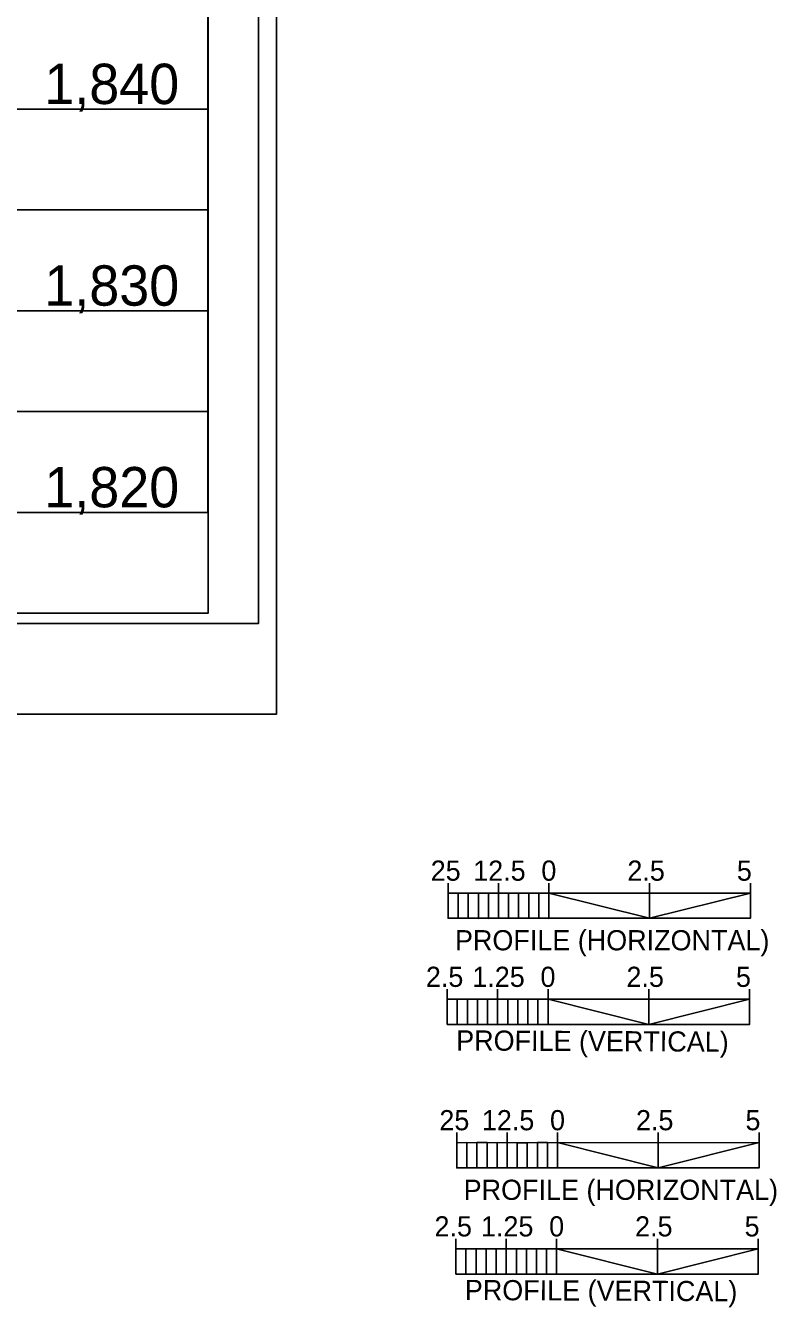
# Model space of a CAD drawing. Extents: x 557032 to 558840, y 515971 to 517218.
# Drawn here: x 558654.2 to 558840.4, y 515971 to 516288.9 of the extents above; entities that cross this region are included whole.
import ezdxf

# ---------------------------------------------------------------- set-up
doc = ezdxf.new("R2010")
doc.units = 0
for name, color, linetype in [('Exist Vertical Profile Vertical Axis Label', 7, 'Continuous'), ('Scratch_Level_5', 7, 'Continuous'), ('Sheet Cutting Line CELL', 7, 'Continuous'), ('Sheet DOT Grid CELL', 7, 'Continuous'), ('Sheet Plot Border Inside CELL', 7, 'Continuous'), ('Sheet Plot Border Outside CELL', 7, 'Continuous'), ('Sheet Profile CELL', 7, 'Continuous'), ('Sheet Profile Grid Major CELL', 7, 'Continuous'), ('Sheet Profile Grid Middle CELL', 7, 'Continuous'), ('Sheet Title CELL', 7, 'Continuous')]:
    doc.layers.add(name, color=color, linetype=linetype)

msp = doc.modelspace()

# ---------------------------------------------------------------- linework, layer by layer
at = {"layer": 'Scratch_Level_5'}
msp.add_lwpolyline([(558074.45, 516168.17), (558699.34, 516168.17), (558699.34, 516568.17), (558074.45, 516568.17)], close=True, dxfattribs=at)
at = {"layer": 'Sheet Cutting Line CELL'}
msp.add_line((557032.45, 516118.17), (558716.45, 516118.17), dxfattribs=at)
at = {"layer": 'Sheet DOT Grid CELL'}
for p, q in [((557199.45, 516268.17), (558699.34, 516268.17)), ((557199.45, 516218.17), (558699.34, 516218.17))]:
    msp.add_line(p, q, dxfattribs=at)
at = {"layer": 'Sheet Plot Border Inside CELL'}
msp.add_lwpolyline([(557045.45, 516140.62), (558711.95, 516140.62), (558711.95, 517195.72), (557045.45, 517195.72)], close=True, dxfattribs=at)
at = {"layer": 'Sheet Plot Border Outside CELL'}
msp.add_lwpolyline([(557032.45, 516118.17), (558716.45, 516118.17), (558716.45, 517218.17), (557032.45, 517218.17)], close=True, dxfattribs=at)
at = {"layer": 'Sheet Profile CELL'}
for p, q in [((558699.45, 516168.17), (557199.45, 516168.17)), ((557199.45, 516143.17), (558699.45, 516143.17))]:
    msp.add_line(p, q, dxfattribs=at)
msp.add_lwpolyline([(558699.45, 517193.17), (557199.45, 517193.17), (557199.45, 516143.17), (558699.45, 516143.17)], close=True, dxfattribs=at)
at = {"layer": 'Sheet Profile Grid Major CELL'}
for points in [[(558559.12, 516268.17), (557199.45, 516268.17), (557199.45, 516268.17), (557199.45, 516218.17), (558699.45, 516218.17)], [(558699.45, 516268.17), (558644.45, 516268.17)], [(558699.45, 516168.17), (557199.45, 516168.17)]]:
    msp.add_lwpolyline(points, dxfattribs=at)
at = {"layer": 'Sheet Profile Grid Middle CELL'}
for points in [[(558699.45, 516293.17), (557199.45, 516293.17), (557199.45, 516243.17), (558699.45, 516243.17)], [(558699.45, 516193.17), (557199.45, 516193.17)]]:
    msp.add_lwpolyline(points, dxfattribs=at)
at = {"layer": 'Sheet Title CELL'}
for p, q in [((558759, 516073.75), (558759, 516076.26)), ((558759, 516073.75), (558759, 516076.26)), ((558759, 516076.26), (558759, 516076.26)), ((558771.5, 516073.75), (558771.5, 516076.26)), ((558771.5, 516073.75), (558771.5, 516076.26)), ((558784, 516073.76), (558784, 516076.25)), ((558784, 516073.76), (558784, 516076.25)), ((558809, 516073.76), (558809, 516076.26)), ((558809, 516073.76), (558809, 516076.26)), ((558834, 516073.76), (558834, 516076.26)), ((558834, 516073.76), (558834, 516076.26)), ((558834, 516073.76), (558759, 516073.75)), ((558834, 516073.76), (558759, 516073.75)), ((558759, 516073.75), (558759, 516067.51)), ((558759, 516073.75), (558759, 516073.75)), ((558759, 516073.75), (558759, 516073.75)), ((558776.5, 516073.75), (558776.5, 516067.51)), ((558809, 516073.76), (558809, 516067.51)), ((558834, 516067.51), (558834, 516073.76)), ((558759, 516067.51), (558834, 516067.51)), ((558758.78, 516047.42), (558758.78, 516049.93)), ((558758.78, 516047.42), (558758.78, 516049.93)), ((558758.78, 516047.42), (558758.78, 516049.93)), ((558758.78, 516049.93), (558758.78, 516049.93)), ((558833.78, 516047.43), (558758.78, 516047.42)), ((558833.78, 516047.43), (558758.78, 516047.42)), ((558833.78, 516047.43), (558758.78, 516047.42)), ((558758.78, 516047.42), (558758.78, 516041.18)), ((558758.78, 516047.42), (558758.78, 516047.42)), ((558758.78, 516047.42), (558758.78, 516047.42)), ((558758.78, 516047.42), (558758.78, 516047.42)), ((558771.28, 516047.43), (558771.28, 516049.92)), ((558771.28, 516047.43), (558771.28, 516049.92)), ((558771.28, 516047.43), (558771.28, 516049.92)), ((558776.28, 516047.42), (558776.28, 516041.17)), ((558783.78, 516047.43), (558783.78, 516049.92)), ((558783.78, 516047.43), (558783.78, 516049.92)), ((558783.78, 516047.43), (558783.78, 516049.92)), ((558808.78, 516047.42), (558808.78, 516049.93)), ((558808.78, 516047.42), (558808.78, 516049.93)), ((558808.78, 516047.42), (558808.78, 516049.93)), ((558808.78, 516047.42), (558808.78, 516041.17)), ((558833.78, 516047.43), (558833.78, 516049.92)), ((558833.78, 516047.43), (558833.78, 516049.92)), ((558833.78, 516047.43), (558833.78, 516049.92)), ((558833.78, 516041.18), (558833.78, 516047.43)), ((558758.78, 516041.18), (558833.78, 516041.18)), ((558761.15, 516011.87), (558761.15, 516014.38)), ((558761.15, 516011.87), (558761.15, 516014.38)), ((558761.15, 516014.38), (558761.15, 516014.38)), ((558773.65, 516011.87), (558773.65, 516014.38)), ((558773.65, 516011.87), (558773.65, 516014.38)), ((558786.15, 516011.88), (558786.15, 516014.37)), ((558786.15, 516011.88), (558786.15, 516014.37)), ((558811.15, 516011.88), (558811.15, 516014.38)), ((558811.15, 516011.88), (558811.15, 516014.38)), ((558836.15, 516011.88), (558836.15, 516014.38)), ((558836.15, 516011.88), (558836.15, 516014.38)), ((558836.15, 516011.88), (558761.15, 516011.87)), ((558836.15, 516011.88), (558761.15, 516011.87)), ((558761.15, 516011.87), (558761.15, 516005.63)), ((558761.15, 516011.87), (558761.15, 516011.87)), ((558761.15, 516011.87), (558761.15, 516011.87)), ((558778.65, 516011.87), (558778.65, 516005.63)), ((558811.15, 516011.88), (558811.15, 516005.63)), ((558836.15, 516005.63), (558836.15, 516011.88)), ((558761.15, 516005.63), (558836.15, 516005.63)), ((558760.93, 515985.54), (558760.93, 515988.05)), ((558760.93, 515985.54), (558760.93, 515988.05)), ((558760.93, 515985.54), (558760.93, 515988.05)), ((558760.93, 515988.05), (558760.93, 515988.05)), ((558773.43, 515985.55), (558773.43, 515988.04)), ((558773.43, 515985.55), (558773.43, 515988.04)), ((558773.43, 515985.55), (558773.43, 515988.04)), ((558785.93, 515985.55), (558785.93, 515988.04)), ((558785.93, 515985.55), (558785.93, 515988.04)), ((558785.93, 515985.55), (558785.93, 515988.04)), ((558810.93, 515985.54), (558810.93, 515988.05)), ((558810.93, 515985.54), (558810.93, 515988.05)), ((558810.93, 515985.54), (558810.93, 515988.05)), ((558835.93, 515985.55), (558835.93, 515988.04)), ((558835.93, 515985.55), (558835.93, 515988.04)), ((558835.93, 515985.55), (558835.93, 515988.04)), ((558835.93, 515985.55), (558760.93, 515985.54)), ((558835.93, 515985.55), (558760.93, 515985.54)), ((558835.93, 515985.55), (558760.93, 515985.54)), ((558760.93, 515985.54), (558760.93, 515979.3)), ((558760.93, 515985.54), (558760.93, 515985.54)), ((558760.93, 515985.54), (558760.93, 515985.54)), ((558760.93, 515985.54), (558760.93, 515985.54)), ((558778.43, 515985.54), (558778.43, 515979.29)), ((558810.93, 515985.54), (558810.93, 515979.29)), ((558835.93, 515979.3), (558835.93, 515985.55)), ((558760.93, 515979.3), (558835.93, 515979.3))]:
    msp.add_line(p, q, dxfattribs=at)
for points in [[(558759, 516073.75), (558761.5, 516073.76), (558761.5, 516067.51), (558759, 516067.51)], [(558764, 516073.76), (558766.5, 516073.76), (558766.5, 516067.5), (558764, 516067.51)], [(558769, 516073.76), (558771.5, 516073.75), (558771.5, 516067.51), (558769, 516067.5)], [(558774, 516073.75), (558776.5, 516073.75), (558776.5, 516067.51), (558774, 516067.51)], [(558779, 516073.76), (558781.5, 516073.76), (558781.5, 516067.51), (558779, 516067.51)], [(558784, 516073.76), (558809, 516067.51), (558784, 516067.5)], [(558834, 516073.76), (558809, 516067.51), (558834, 516067.51)], [(558758.78, 516047.42), (558761.28, 516047.42), (558761.28, 516041.17), (558758.78, 516041.18)], [(558763.78, 516047.43), (558766.28, 516047.43), (558766.28, 516041.18), (558763.78, 516041.18)], [(558768.78, 516047.43), (558771.28, 516047.43), (558771.28, 516041.17), (558768.78, 516041.18)], [(558773.78, 516047.42), (558776.28, 516047.42), (558776.28, 516041.17), (558773.78, 516041.18)], [(558778.78, 516047.42), (558781.28, 516047.43), (558781.28, 516041.18), (558778.78, 516041.18)], [(558783.78, 516047.43), (558808.78, 516041.17), (558783.78, 516041.18)], [(558833.78, 516047.43), (558808.78, 516041.17), (558833.78, 516041.18)], [(558761.15, 516011.87), (558763.65, 516011.88), (558763.65, 516005.63), (558761.15, 516005.63)], [(558766.15, 516011.88), (558768.65, 516011.88), (558768.65, 516005.62), (558766.15, 516005.63)], [(558771.15, 516011.88), (558773.65, 516011.87), (558773.65, 516005.63), (558771.15, 516005.62)], [(558776.15, 516011.87), (558778.65, 516011.87), (558778.65, 516005.63), (558776.15, 516005.63)], [(558781.15, 516011.88), (558783.65, 516011.88), (558783.65, 516005.63), (558781.15, 516005.63)], [(558786.15, 516011.88), (558811.15, 516005.63), (558786.15, 516005.62)], [(558836.15, 516011.88), (558811.15, 516005.63), (558836.15, 516005.63)], [(558760.93, 515985.54), (558763.43, 515985.54), (558763.43, 515979.29), (558760.93, 515979.3)], [(558765.93, 515985.55), (558768.43, 515985.55), (558768.43, 515979.3), (558765.93, 515979.3)], [(558770.93, 515985.55), (558773.43, 515985.55), (558773.43, 515979.29), (558770.93, 515979.3)], [(558775.93, 515985.54), (558778.43, 515985.54), (558778.43, 515979.29), (558775.93, 515979.3)], [(558780.93, 515985.54), (558783.43, 515985.55), (558783.43, 515979.3), (558780.93, 515979.3)], [(558785.93, 515985.55), (558810.93, 515979.29), (558785.93, 515979.3)], [(558835.93, 515985.55), (558810.93, 515979.29), (558835.93, 515979.3)]]:
    msp.add_lwpolyline(points, close=True, dxfattribs=at)

# ---------------------------------------------------------------- texts
at = {"layer": 'Exist Vertical Profile Vertical Axis Label'}
for s, p in [('1,840', (558658.81, 516269.42)), ('1,830', (558658.81, 516219.42)), ('1,820', (558658.81, 516169.42))]:
    msp.add_text(s, height=10, dxfattribs=at).set_placement(p)
at = {"layer": 'Sheet Title CELL'}
for s, rotation, p in [('25', 360, (558754.68, 516076.83)), ('12.5', 360, (558765.22, 516076.83)), ('0', 360, (558782.13, 516076.83)), ('2.5', 360, (558803.47, 516076.83)), ('5', 360, (558830.64, 516076.83)), ('PROFILE (HORIZONTAL)', 360, (558760.7, 516059.57)), ('2.5', 360, (558753.48, 516050.5)), ('1.25', 360, (558765, 516050.5)), ('0', 360, (558781.91, 516050.5)), ('2.5', 360, (558803.25, 516050.5)), ('5', 360, (558830.42, 516050.5)), ('PROFILE (VERTICAL)', 359.7282, (558760.99, 516034.73)), ('25', 360, (558756.83, 516014.95)), ('12.5', 360, (558767.37, 516014.95)), ('0', 360, (558784.28, 516014.95)), ('2.5', 360, (558805.61, 516014.95)), ('5', 360, (558832.78, 516014.95)), ('PROFILE (HORIZONTAL)', 360, (558762.85, 515997.69)), ('2.5', 360, (558755.62, 515988.62)), ('1.25', 360, (558767.15, 515988.62)), ('0', 360, (558784.06, 515988.62)), ('2.5', 360, (558805.39, 515988.62)), ('5', 360, (558832.56, 515988.62)), ('PROFILE (VERTICAL)', 359.7282, (558763.13, 515972.85))]:
    msp.add_text(s, height=5, rotation=rotation, dxfattribs=at).set_placement(p)

doc.saveas('drawing.dxf')
